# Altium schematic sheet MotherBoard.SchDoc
size A2
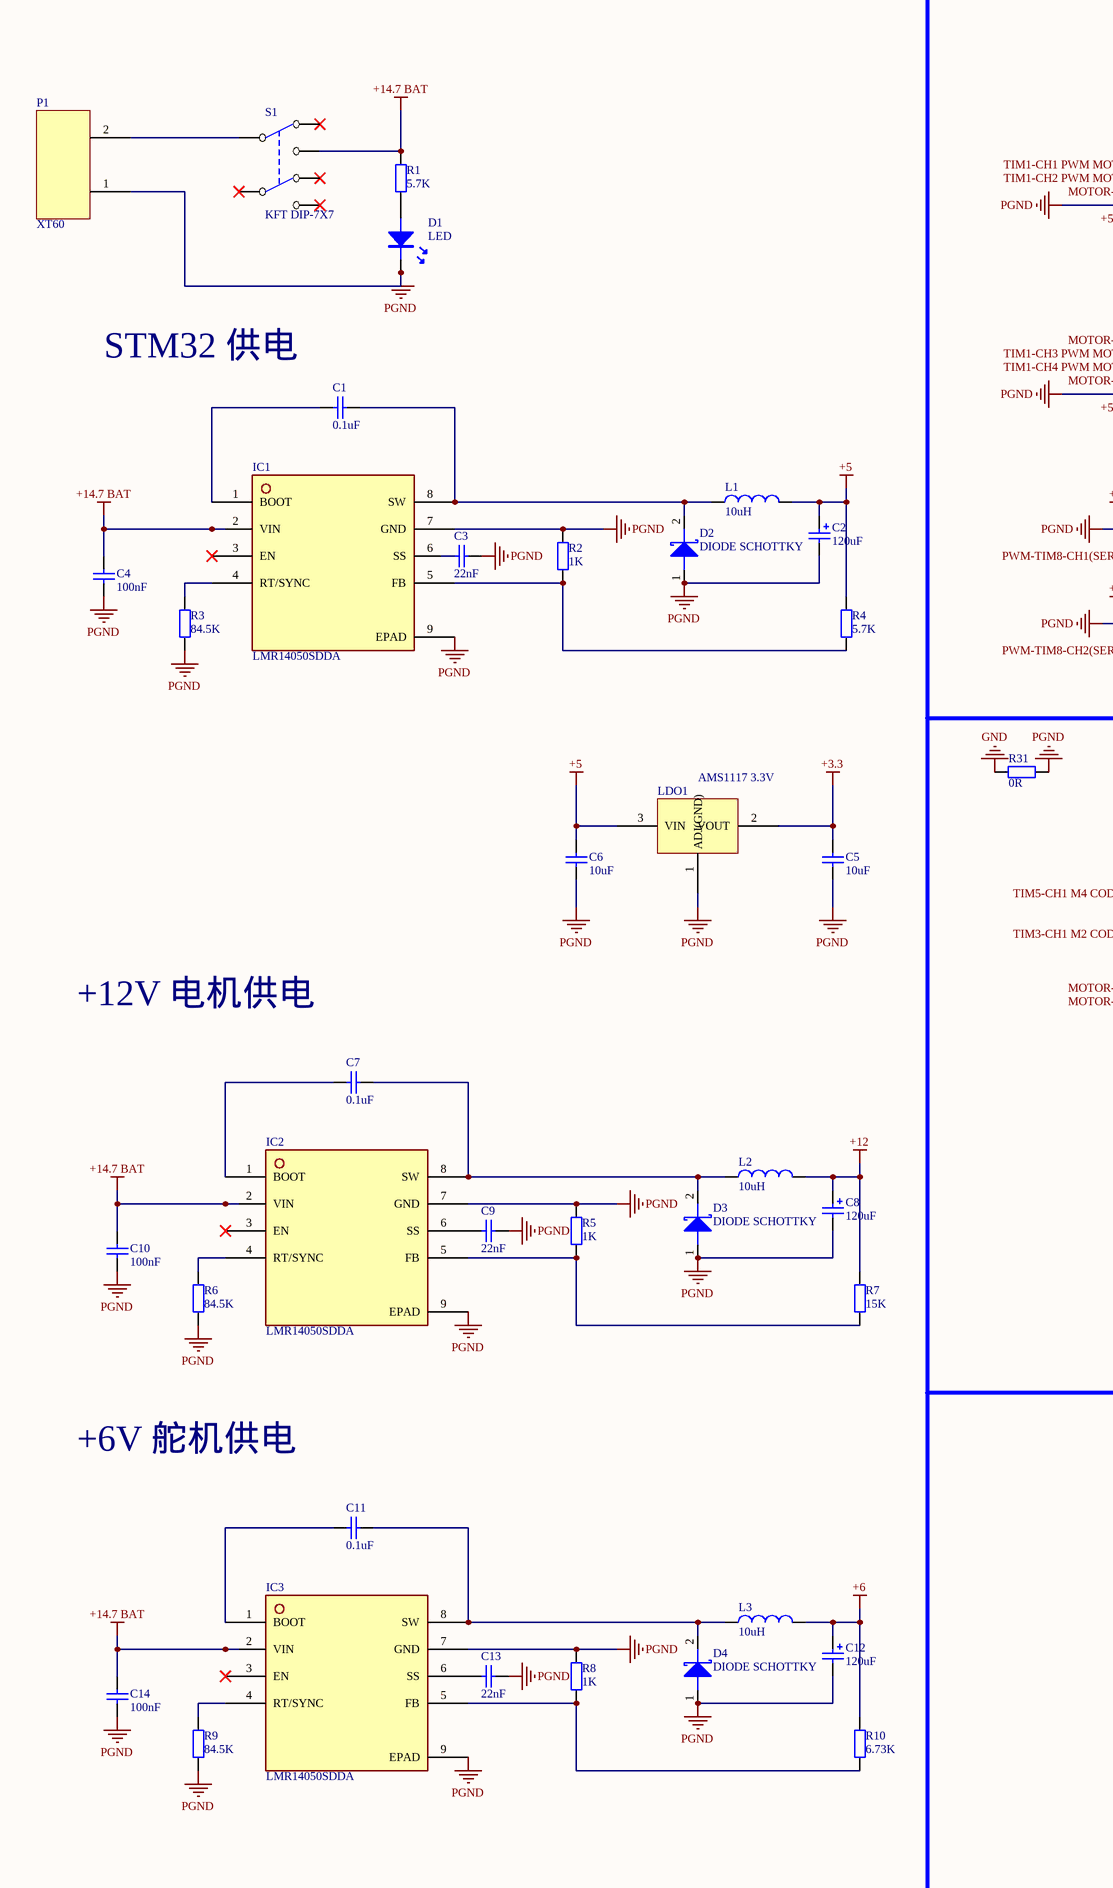
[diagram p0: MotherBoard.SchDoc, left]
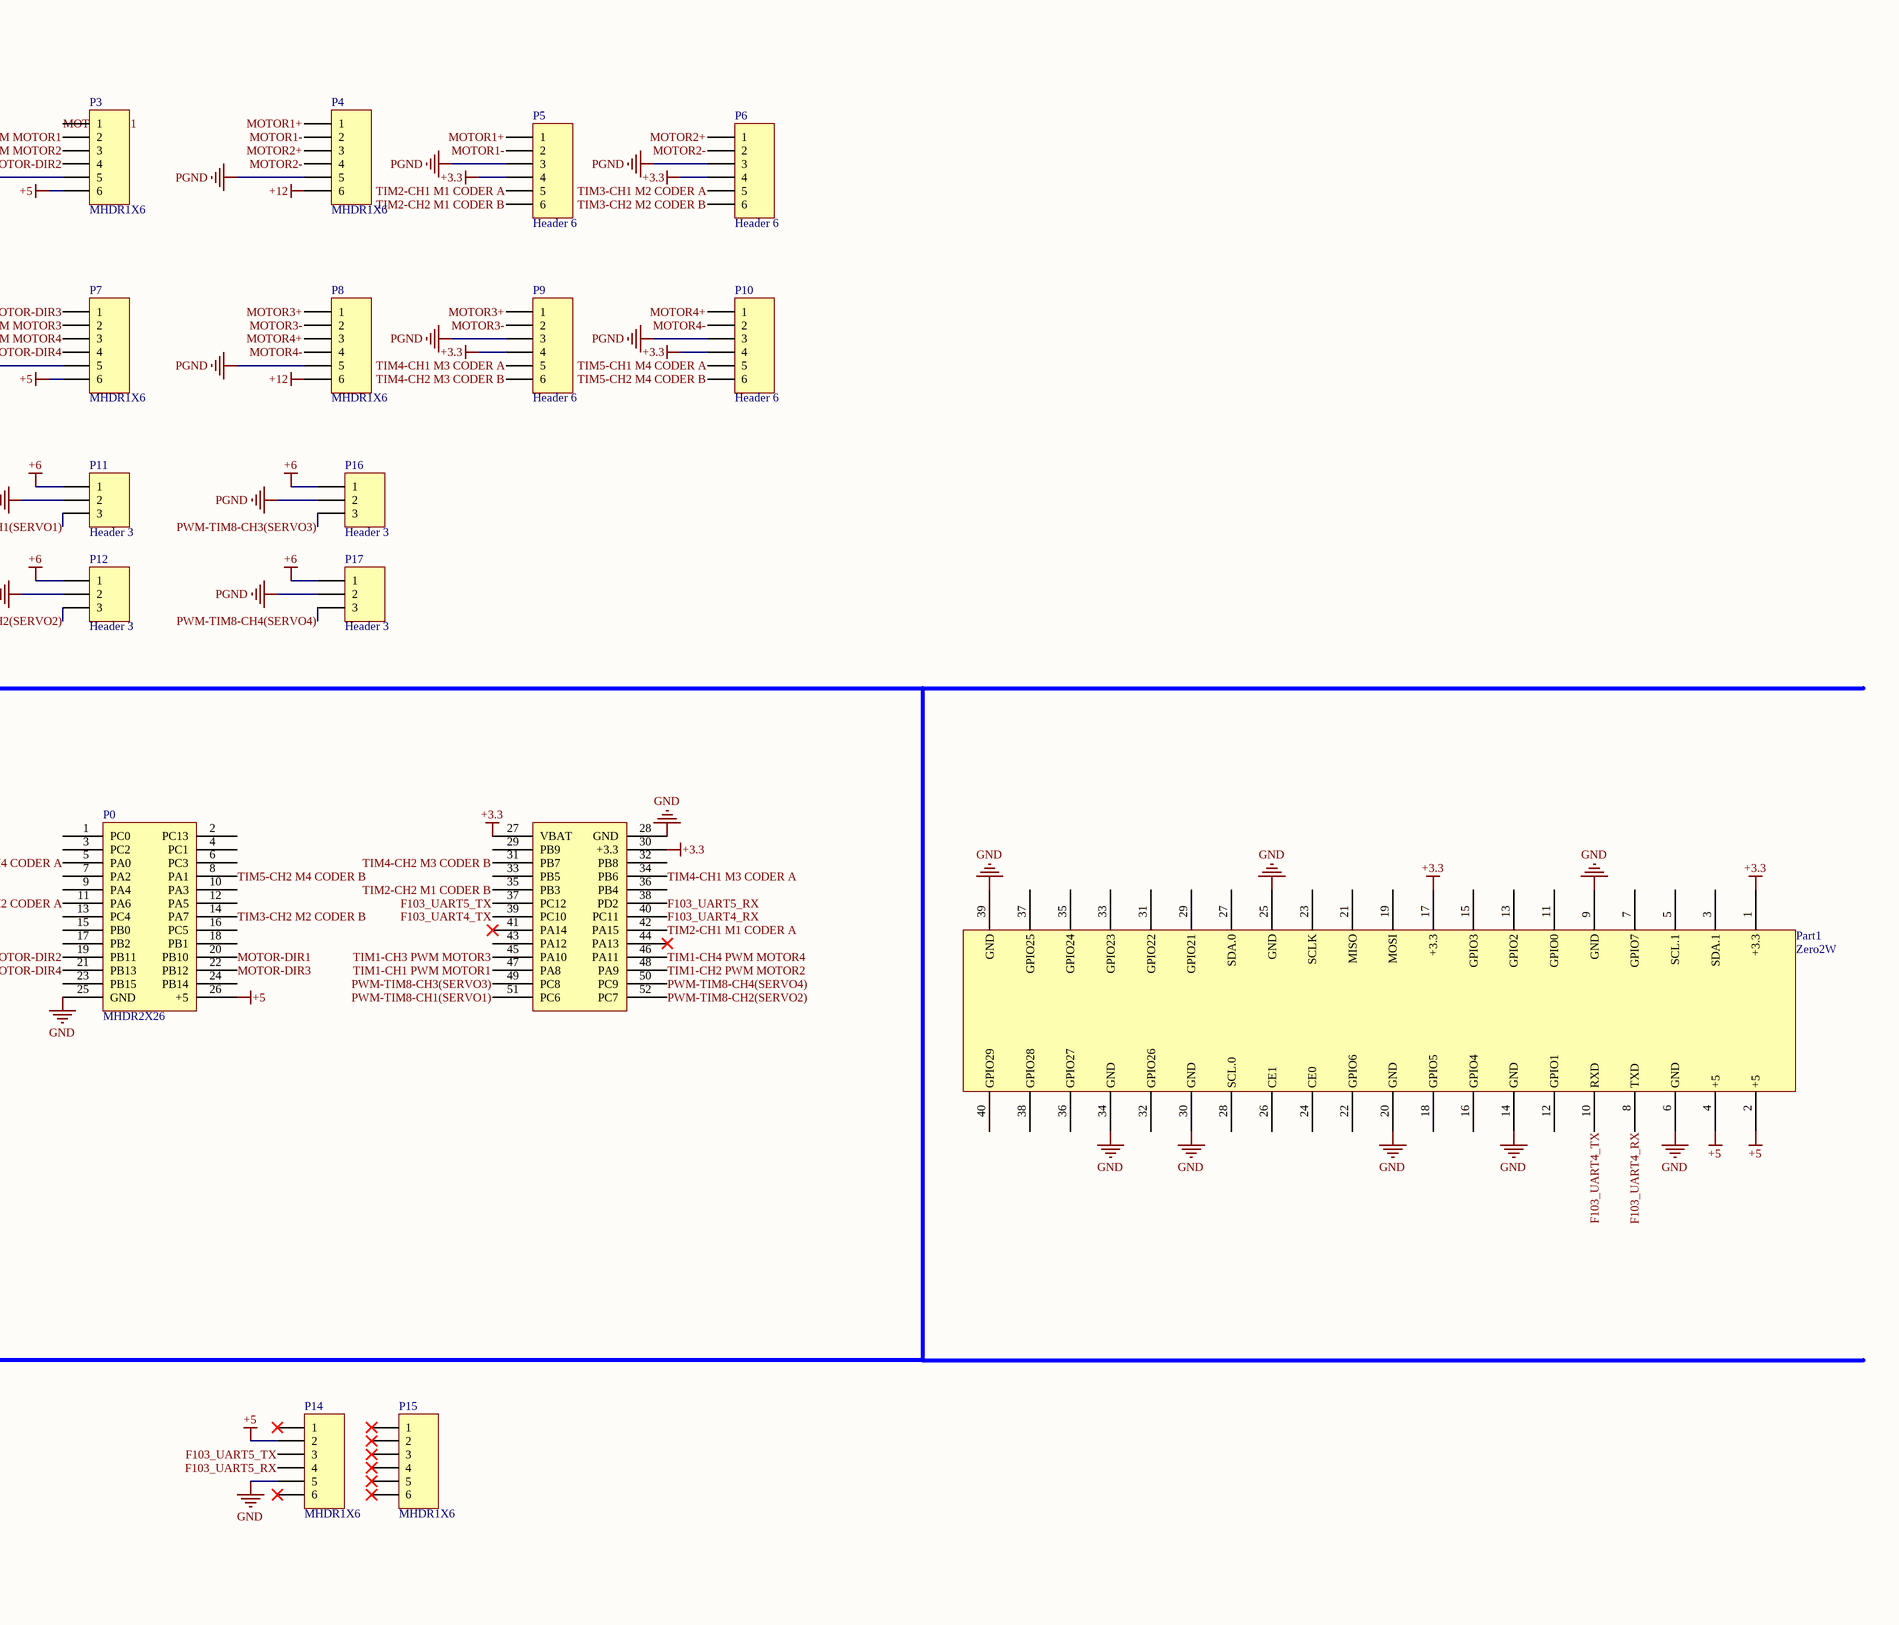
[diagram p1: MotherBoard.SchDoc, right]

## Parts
C1  0.1uF  [CAPC2012X10M]
C2  120uF  [CAP 6.3x15]
C3  22nF  [CAPC2012X10M]
C4  100nF  [CAPC2012X10M]
C5  10uF  [CAPC2012X10M]
C6  10uF  [CAPC2012X10M]
C7  0.1uF  [CAPC2012X10M]
C8  120uF  [CAP 6.3x15]
C9  22nF  [CAPC2012X10M]
C10  100nF  [CAPC2012X10M]
C11  0.1uF  [CAPC2012X10M]
C12  120uF  [CAP 6.3x15]
C13  22nF  [CAPC2012X10M]
C14  100nF  [CAPC2012X10M]
D1  LED  [LED-0805]
D2  DIODE SCHOTTKY  [SMA]
D3  DIODE SCHOTTKY  [SMA]
D4  DIODE SCHOTTKY  [SMA]
IC1  LMR14050SDDA  [SOP127P600X170_HS-9M]
IC2  LMR14050SDDA  [SOP127P600X170_HS-9M]
IC3  LMR14050SDDA  [SOP127P600X170_HS-9M]
L1  10uH  [INDP4442X20M]
L2  10uH  [INDP4442X20M]
L3  10uH  [INDP4442X20M]
LDO1  AMS1117 3.3V  [SOT230P700X180-4M]
P0  MHDR2X26  [PCBComponent_1]
P1  XT60  [XT60H-F]
P3  MHDR1X6  [MPIN-6-2.54-1.0]
P4  MHDR1X6  [MPIN-6-2.54-1.0]
P5  Header 6  [HDR1X6]
P6  Header 6  [HDR1X6]
P7  MHDR1X6  [MPIN-6-2.54-1.0]
P8  MHDR1X6  [MPIN-6-2.54-1.0]
P9  Header 6  [HDR1X6]
P10  Header 6  [HDR1X6]
P11  Header 3  [HDR1X3]
P12  Header 3  [HDR1X3]
P14  MHDR1X6  [MPIN-6-2.54-1.0]
P15  MHDR1X6  [MPIN-6-2.54-1.0]
P16  Header 3  [HDR1X3]
P17  Header 3  [HDR1X3]
Part1  Zero2W  [Zero2W]
R1  5.7K  [0805]
R2  1K  [0805]
R3  84.5K  [0805]
R4  5.7K  [0805]
R5  1K  [0805]
R6  84.5K  [0805]
R7  15K  [0805]
R8  1K  [0805]
R9  84.5K  [0805]
R10  6.73K  [0805]
R31  0R  [0805]
S1  KFT DIP-7X7  [7X7 DIP]

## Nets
+3.3: C5.2 LDO1.2(VOUT) P0.27(VBAT) P0.30(+3.3) P5.4 P6.4 P9.4 P10.4 Part1.1(+3.3) Part1.17(+3.3)
+5: C2.1 C6.2 L1.2 LDO1.3(VIN) P0.26(+5) P3.6 P7.6 P14.2 Part1.2(+5) Part1.4(+5) R4.2
+6: C12.1 L3.2 P11.1 P12.1 P16.1 P17.1 R10.2
+12: C8.1 L2.2 P4.6 P8.6 R7.2
+14.7 BAT: C4.2 C10.2 C14.2 IC1.2(VIN) IC2.2(VIN) IC3.2(VIN) R1.2 S1.1
GND: P0.25(GND) P0.28(GND) P14.5 Part1.6(GND) Part1.9(GND) Part1.14(GND) Part1.20(GND) Part1.25(GND) Part1.30(GND) Part1.34(GND) Part1.39(GND) R31.2
PGND: C2.2 C3.2 C4.1 C5.1 C6.1 C8.2 C9.2 C10.1 C12.2 C13.2 C14.1 D1.2 D2.1 D3.1 D4.1 IC1.7(GND) IC1.9(EPAD) IC2.7(GND) IC2.9(EPAD) IC3.7(GND) IC3.9(EPAD) LDO1.1(ADJ(GND)) P1.1 P3.5 P4.5 P5.3 P6.3 P7.5 P8.5 P9.3 P10.3 P11.2 P12.2 P16.2 P17.2 R2.2 R3.1 R5.2 R6.1 R8.2 R9.1 R31.1
F103_UART4_RX: P0.40(PC11) Part1.8(TXD)
F103_UART4_TX: P0.39(PC10) Part1.10(RXD)
F103_UART5_RX: P0.38(PD2) P14.4
F103_UART5_TX: P0.37(PC12) P14.3
MOTOR1+: P4.1 P5.1
MOTOR1-: P4.2 P5.2
MOTOR2+: P4.3 P6.1
MOTOR2-: P4.4 P6.2
MOTOR3+: P8.1 P9.1
MOTOR3-: P8.2 P9.2
MOTOR4+: P8.3 P10.1
MOTOR4-: P8.4 P10.2
MOTOR-DIR1: P0.20(PB10) P3.1
MOTOR-DIR2: P0.19(PB11) P3.4
MOTOR-DIR3: P0.22(PB12) P7.1
MOTOR-DIR4: P0.21(PB13) P7.4
PWM-TIM8-CH1(SERVO1): P0.51(PC6) P11.3
PWM-TIM8-CH2(SERVO2): P0.52(PC7) P12.3
PWM-TIM8-CH3(SERVO3): P0.49(PC8) P16.3
PWM-TIM8-CH4(SERVO4): P0.50(PC9) P17.3
TIM1-CH1 PWM MOTOR1: P0.47(PA8) P3.2
TIM1-CH2 PWM MOTOR2: P0.48(PA9) P3.3
TIM1-CH3 PWM MOTOR3: P0.45(PA10) P7.2
TIM1-CH4 PWM MOTOR4: P0.46(PA11) P7.3
TIM2-CH1 M1 CODER A: P0.42(PA15) P5.5
TIM2-CH2 M1 CODER B: P0.35(PB3) P5.6
TIM3-CH1 M2 CODER A: P0.11(PA6) P6.5
TIM3-CH2 M2 CODER B: P0.14(PA7) P6.6
TIM4-CH1 M3 CODER A: P0.34(PB6) P9.5
TIM4-CH2 M3 CODER B: P0.31(PB7) P9.6
TIM5-CH1 M4 CODER A: P0.5(PA0) P10.5
TIM5-CH2 M4 CODER B: P0.8(PA1) P10.6
NetC1_1: C1.1 IC1.1(BOOT)
NetC1_2: C1.2 D2.2 IC1.8(SW) L1.1
NetC3_1: C3.1 IC1.6(SS)
NetC7_1: C7.1 IC2.1(BOOT)
NetC7_2: C7.2 D3.2 IC2.8(SW) L2.1
NetC9_1: C9.1 IC2.6(SS)
NetC11_1: C11.1 IC3.1(BOOT)
NetC11_2: C11.2 D4.2 IC3.8(SW) L3.1
NetC13_1: C13.1 IC3.6(SS)
NetD1_1: D1.1 R1.1
NetIC1_4: IC1.4(RT/SYNC) R3.2
NetIC1_5: IC1.5(FB) R2.1 R4.1
NetIC2_4: IC2.4(RT/SYNC) R6.2
NetIC2_5: IC2.5(FB) R5.1 R7.1
NetIC3_4: IC3.4(RT/SYNC) R9.2
NetIC3_5: IC3.5(FB) R8.1 R10.1
NetP1_2: P1.2 S1.2

Not connected (* = marked no-connect by the designer): IC1 3(EN)*; IC2 3(EN)*; IC3 3(EN)*; P0 1(PC0) 2(PC13) 3(PC2) 4(PC1) 6(PC3) 7(PA2) 9(PA4) 10(PA3) 12(PA5) 13(PC4) 15(PB0) 16(PC5) 17(PB2) 18(PB1) 23(PB15) 24(PB14) 29(PB9) 32(PB8) 33(PB5) 36(PB4) 41(PA14)* 43(PA12) 44(PA13)*; P14 1* 6*; P15 1* 2* 3* 4* 5* 6*; Part1 3(SDA.1) 5(SCL.1) 7(GPIO7) 11(GPIO0) 12(GPIO1) 13(GPIO2) 15(GPIO3) 16(GPIO4) 18(GPIO5) 19(MOSI) 21(MISO) 22(GPIO6) 23(SCLK) 24(CE0) 26(CE1) 27(SDA.0) 28(SCL.0) 29(GPIO21) 31(GPIO22) 32(GPIO26) 33(GPIO23) 35(GPIO24) 36(GPIO27) 37(GPIO25) 38(GPIO28) 40(GPIO29); S1 3* 4* 5* 6*

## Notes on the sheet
- STM32 供电
- +12V 电机供电
- +6V 舵机供电

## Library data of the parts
C1 = Cap: Capacitor 0.1uF
C2 C8 C12 = Cap Pol: Polarized Capacitor (Radial)
C3-C7 C9-C11 C13 C14 = Cap: Capacitor
D2-D4 = DIODE SCHOTTKY: 肖特基二极管
L1-L3 = Inductor: Code_IEC: 1005
P0 = MHDR2X26: Header, 52-Pin, Dual row
P3 P4 P7 P8 P14 P15 = MHDR1X6: Header, 6-Pin
P5 P6 P9 P10 = Header 6: Header, 6-Pin
P11 P12 P16 P17 = Header 3: Header, 3-Pin
R1-R10 R31 = Res: Resistor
